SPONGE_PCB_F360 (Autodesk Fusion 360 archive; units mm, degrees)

design "Form-Leiterplatte"
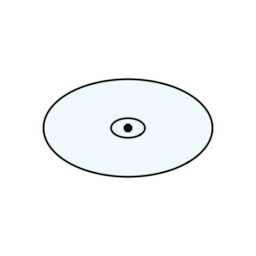
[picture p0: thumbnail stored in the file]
sketch "Skizze" plane through (0, 0, 0) normal (0, 0, 1) x axis (1, 0, 0)
  circle C1 centre (0, 0) radius 5.5
  circle C2 centre (0, 0) radius 27.5
  point P1 (0, 0)
  point P2 (0, 0)
  point P3 (0, 0)
  coincident P1 P2
  coincident P1 P3
  dimension "d10" diameter C1 = 11
  dimension "d11" diameter C2 = 55
  dimension "d2" distance = 16.75
  dimension "d3" distance = 19.174
  dimension "d4" distance = 5.25
  dimension "d5" distance = 5.25
  dimension "d6" distance = 5.3
  dimension "d7" radius = 28

design "Haley_3D_Leiterplatte" references "Form-Leiterplatte"
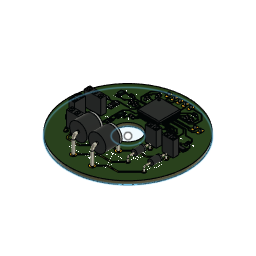
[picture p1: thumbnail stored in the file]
external_derived "Extern abgeleitet"
sketch "Skizze" plane through (0, 0, 0) normal (0, 0, 1) x axis (1, 0, 0)
  circle C1 centre (0, 0) radius 27.5
  circle C2 centre (0, 0) radius 5.5
canvas "Ansichtsbereich1" bodies "Leiterplatte"
canvas "Ansichtsbereich2" bodies "Leiterplatte"
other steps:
derived_base_feature "Abgeleitetes Basiselement"
base_feature "Basiselement1"
base_feature "Basiselement1"
base_feature "Basiselement1"
base_feature "Basiselement1"
base_feature "Basiselement1"
base_feature "Basiselement1"
base_feature "Basiselement1"
base_feature "Basiselement1"
base_feature "Basiselement1"
base_feature "Basiselement1"
base_feature "Basiselement1"
base_feature "Basiselement1"
base_feature "Basiselement1"
base_feature "Basiselement1"
base_feature "Basiselement1"
base_feature "Basiselement1"
base_feature "Basiselement1"
pcbextrude "Leiterplatte extrudieren1"
pcbextrude "Leiterplatte extrudieren1"
pcbextrude "Leiterplatte extrudieren1"
pcbextrude "Leiterplatte extrudieren1"
base_feature "Basiselement1"
base_feature "Basiselement1"
extrude "Extrusion" sketch "Skizze" blind 1.5 bodies "Leiterplatte"
pcbextrude "Leiterplatte extrudieren1"
pcbextrude "Leiterplatte extrudieren2"
create_component "Komponente erstellen1"
create_component "Komponente erstellen2"
create_component "Komponente erstellen3"
create_component "Komponente erstellen4"
create_component "Komponente erstellen5"
create_component "Komponente erstellen6"
as_built_joint "Bestand"
create_component "Komponente erstellen6"
create_component "Komponente erstellen8"
create_component "Komponente erstellen1"
create_component "Komponente erstellen144"
create_component "Komponente erstellen204"
create_component "Komponente erstellen205"
create_component "Komponente erstellen1"
create_component "Komponente erstellen206"
create_component "Komponente erstellen1"
create_component "Komponente erstellen207"
create_component "Komponente erstellen1"
create_component "Komponente erstellen208"
create_component "Komponente erstellen1"
create_component "Komponente erstellen209"
create_component "Komponente erstellen1"
create_component "Komponente erstellen210"
create_component "Komponente erstellen211"
create_component "Komponente erstellen212"
create_component "Komponente erstellen213"
named bodies: "Leiterplatte"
